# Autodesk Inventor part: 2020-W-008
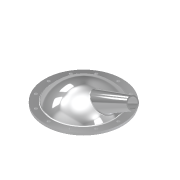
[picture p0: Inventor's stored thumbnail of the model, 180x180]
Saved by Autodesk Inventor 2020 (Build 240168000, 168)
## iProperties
Created: 2013-12
Part Number: 2020-W-008
Material: Aluminium 6061
Document SubType Name: Modeling
Designer: F.Stasiak
Density: 2.7 g/cm^3
Appearance: Aluminium — płaski
Manager: www.cadconsulting.pl
Company: Fabian Stasiak CAD Consulting
Author: F.Stasiak
Subject: Zbiór ćwiczeń. Autodesk Inventor 2020. Kurs podstawowy
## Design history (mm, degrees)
sketch "Szkic1"
  geometry: L1 (0, 0)-(200, 0); L2 (0, 0)-(0, 100); A1 r 250 centre (0, -150) between (200, 0) and (0, 100); 1 further point
  constraints: 4 end point, 2 point on circle, 1 centre point, 1 coincident, 1 horizontal, 1 vertical, 1 vertical alignment
  dimensions: "d0" = 150 distance of point (0, 0) A1.centre; "d1" = 250 radius of A1
revolve "Obrót1" sketch "Szkic1" stored, may be unused: angle "d2" = 90 deg
feature "Skorupa1" dims "d3" = 12
sketch "Szkic2"
  geometry: C1 r 184.781 at (0, 0) reference; C2 r 200 at (0, 0) reference; C3 r 250 at (0, 0)
  constraints: 1 centre point
  dimensions: "d4" = 500 diameter of C3
extrude "Wyciągnięcie proste1" join sketch "Szkic2" distance "d5" = 15; taper "d6" = 0 deg
sketch "Szkic3"
  geometry: L1 (0, 0)-(317.208, 147.916); L2 (-362.461, 0)-(424.769, 0) reference
  constraints: 2 end point
  dimensions: "d7" = 350 distance of L1.start L1.end; "d8" = 25 deg angle of L1 L2
node "Płaszczyzna konstrukcyjna1"
sketch "Szkic4"
  geometry: C1 r 30 at (0, 0); C2 r 37.5 at (0, 0); 1 further point
  constraints: 2 centre point, 2 coincident
  dimensions: "d9" = 60 diameter of C1; "d10" = 75 diameter of C2
extrude "Wyciągnięcie proste2" join sketch "Szkic4" stored distance "d11" = 15; taper "d12" = 5 deg
extrude "Wyciągnięcie proste3" cut sketch "Szkic4" stored distance "d13" = 15; taper "d14" = 5 deg
fillet "Zaokrąglenie1" dims "d15" = 10
sketch "Szkic5" dims "d16" = 450
  geometry: C1 r 250 at (0, 0) reference; 1 further point
  constraints: 2 vertical alignment, 2 other
hole "Otwór1" sketch "Szkic5" at (0, 225) diameter "d17" = 19; stored, may be unused: countersink angle "d21" = 90 deg, drill point angle "d23" = 118 deg; dims "d18" = 6, "d19" = 4, "d20" = 2, "d22" = 8
pattern_circular "Szyk kołowy1" dims angle "d25" = 360 deg
node "Bryła1"
